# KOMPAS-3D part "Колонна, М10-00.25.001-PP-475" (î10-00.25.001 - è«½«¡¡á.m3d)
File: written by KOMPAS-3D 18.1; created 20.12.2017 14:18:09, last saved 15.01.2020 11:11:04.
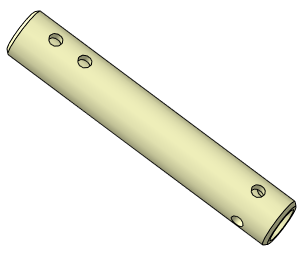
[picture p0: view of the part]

Document properties: Автор: Мирончук; Организация: Мирончук; Полное имя файла: D:\Magna\Магна Ins\Магна ins 10\М10-00.00.000\3Д\М10-00.25.001 - Колонна.m3d

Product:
- Part/product: Колонна  | designation М10-00.25.001-PP-475
    Масса: 2.126
    Раздел спецификации: Детали
    Форматы листов документа: A4
- Part/product: Колонна  | designation М10-00.25.001-PP-425
    Масса: 1.88058
    Раздел спецификации: Детали
    Форматы листов документа: A4
- Part/product: Колонна  | designation М10-00.25.001-PP-375
    Масса: 1.63515
    Раздел спецификации: Детали
    Форматы листов документа: A4
- Part/product: Колонна  | designation М10-00.25.001-PP
    Масса: 1.63515
    Раздел спецификации: Детали
    Форматы листов документа: A4
    source file: М10-00.25.001 - Колонна.cdw

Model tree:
1. Эскиз:1
2. Операция вращения:1
     Угол 1 = 360
3. Эскиз:2  (with: Операция вращения:1)
4. Отверстие:1
     Глубина выреза = 37.5; Диаметр отверстия = 20; Угол конуса торца = 118; Координата X = 50
5. Отверстие:2
     Глубина выреза = 37.5; Диаметр отверстия = 20; Угол конуса торца = 118; Координата X = 299
6. Массив по концентрической сетке:1  (with: Отверстие:1, Операция вращения:1)  (4 pattern instances)
     Шаг 2 = 360
7. Зеркальный массив:1
8. Экземпляр ( 1 )
9. Экземпляр ( 2 )  (with: Отверстие:2)
10. Массив по сетке:1  (with: Отверстие:2, Эскиз:2)  (2 pattern instances)
     Шаг 1 = 50; Угол раствора = 90
11. Эскиз:6  (with: Операция вращения:1)
12. Элемент выдавливания:5
     Расстояние 1 = 18
13. Фаска:4  (with: Операция вращения:1)
     Угол = 45; Длина 1 = 5; Длина 2 = 5

Expressions: 75/2; 50/2; 319+30
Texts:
  PP-375
  PP-425
  PP-475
